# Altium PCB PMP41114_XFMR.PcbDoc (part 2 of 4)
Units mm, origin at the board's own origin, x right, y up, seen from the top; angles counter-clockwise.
Board outline 70 x 173.04 mm, 10 copper layers (Top Layer, Layer 2, Layer 3, Layer 4, Layer 5, Layer 6, Layer 7, Layer 8, Layer 9, Bottom Layer 1), stack 2.98 mm thick; 147 components, 149 nets, 547 pads, 972 vias.
Unrouted connection lines stored in the file: 2.
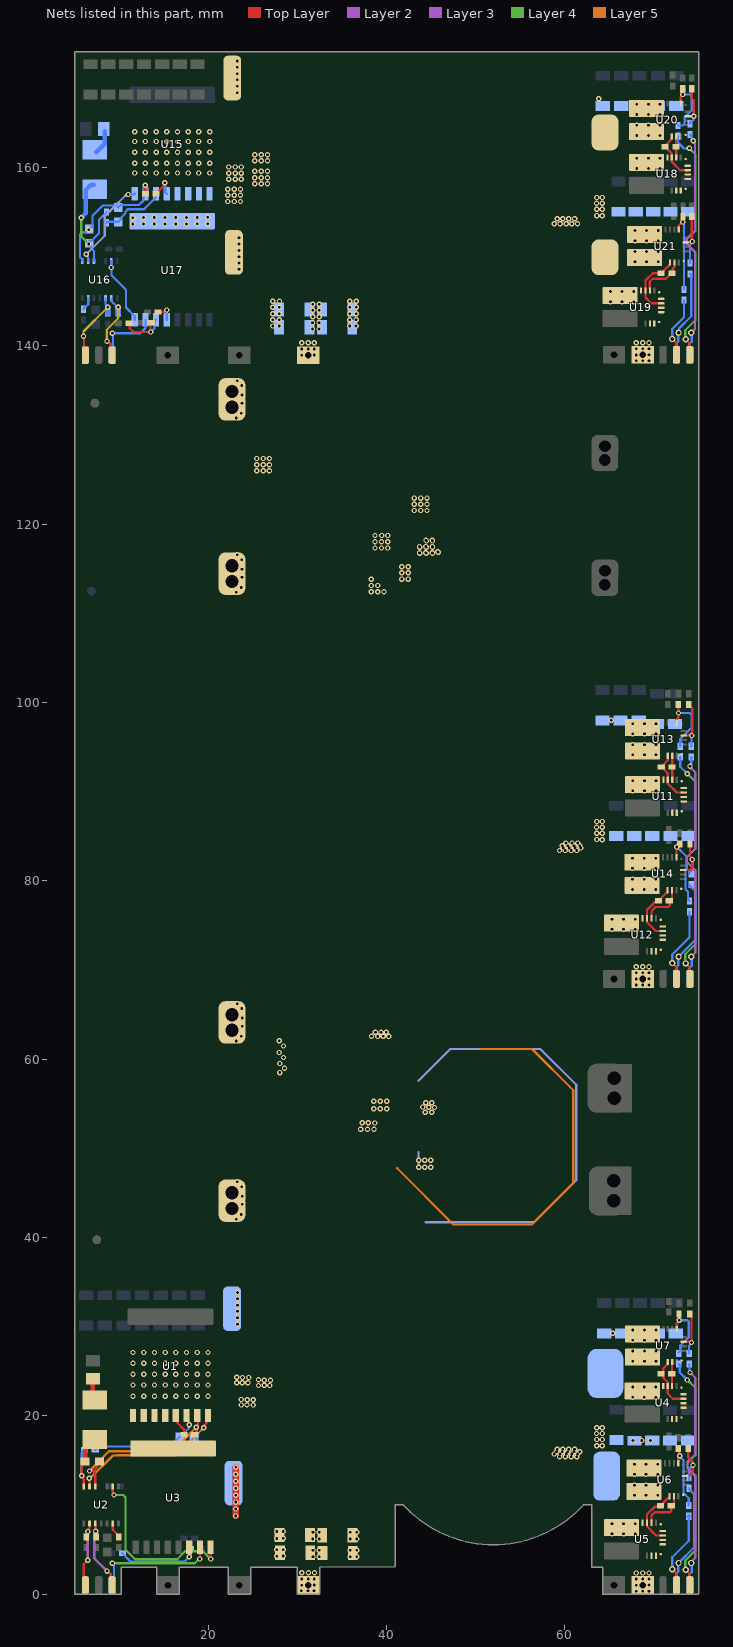
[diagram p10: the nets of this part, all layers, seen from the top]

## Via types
v1: diameter 0.6, hole 0.3, Top Layer to Bottom Layer 1, tented both sides, 748 vias
v2: diameter 0.6, hole 0.3, Layer 2 to Layer 3, tented both sides, 41 vias
v3: diameter 0.6, hole 0.3, Layer 6 to Layer 7, tented both sides, 38 vias
v4: diameter 0.6, hole 0.3, Layer 8 to Layer 9, tented both sides, 35 vias
v5: diameter 0.6, hole 0.3, Layer 4 to Layer 5, tented both sides, 31 vias
v6: diameter 0.6, hole 0.3, Layer 2 to Layer 9, tented both sides, 24 vias
v7: diameter 0.6, hole 0.3, Layer 2 to Layer 5, tented both sides, 22 vias
v8: diameter 0.7, hole 0.4, Top Layer to Bottom Layer 1, tented both sides, 18 vias
v9: diameter 0.6, hole 0.3, Layer 6 to Layer 9, tented both sides, 15 vias

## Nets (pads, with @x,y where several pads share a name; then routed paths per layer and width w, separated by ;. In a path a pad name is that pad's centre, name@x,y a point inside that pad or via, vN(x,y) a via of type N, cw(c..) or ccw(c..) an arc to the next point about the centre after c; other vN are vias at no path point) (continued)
GND-AH_2: C28.2 U4.4 U4.14 U7.8 | length 6.2
  Top Layer w0.254: C28.2@70.789,24.718 70.889,24.718 71.038,24.867 71.038,25.292 71.549,25.804 U7.8@71.549,26.025 ; C28.2@70.865,24.718 71.038,24.545 71.038,24.236 71.526,23.748 71.526,23.335 U4.4@71.528,23.333 71.528,22.488 72.108,21.908 U4.14@73.303,21.908
GND-AH_4: C61.2 U11.4 U11.14 U13.8 | length 5.9
  Top Layer w0.254: C61.2@70.807,92.775 C61.2@70.907,92.775 ; U13.8@71.549,94.025 71.547,94.023 71.547,93.516 71.08,93.048 71.08,92.948 C61.2@70.907,92.775 ; U11.14@73.324,89.908 72.566,89.908 71.549,90.925 U11.4@71.549,91.333 71.549,92.064 71.08,92.534 71.08,92.602 C61.2@70.907,92.775
GND-AH_5: C92.2 U18.4 U18.14 U20.8 | length 5.8
  Top Layer w0.254: C92.2@71.066,162.295 71.018,162.343 C92.2@71.066,162.392 ; C92.2@71.147,162.246 71.247,162.246 C92.2@71.297,162.296 ; C92.2@71.249,162.343 71.349,162.343 71.522,162.17 71.522,162.07 71.998,161.594 71.998,161.14 U18.4@72,161.138 72.002,161.136 72.002,160.622 72.911,159.713 U18.14@73.775,159.713 ; C92.2@71.42,162.419 71.42,162.642 71.99,163.212 U20.8@71.99,163.433
GND-BH_2: C25.2 U5.4 U5.14 U6.8 | length 6.9
  Top Layer w0.254: U5.4@69.21,8.005 69.212,8.003 69.212,7.595 70.227,6.58 U5.14@70.985,6.58 ; U5.4@69.212,8.005 69.212,8.103 69.21,8.105 69.21,8.947 70.099,9.835 70.653,9.835 C25.2@70.731,9.913 ; C25.2@70.802,9.843 71.004,10.045 71.004,10.228 71.331,10.555 71.34,10.555 71.537,10.752 U6.8@71.723,10.752 ; C25.2@70.998,9.75 70.994,9.75 C25.2@71.004,9.74
GND-BH_4: C62.2 U12.4 U12.14 U14.8 | length 6.7
  Top Layer w0.254: U12.4@69.21,75.805 69.212,75.803 69.212,75.355 70.187,74.38 U12.14@70.985,74.38 ; U12.4@69.21,76.005 69.212,76.007 69.212,76.742 70.107,77.638 70.328,77.638 70.501,77.811 70.601,77.811 70.774,77.984 70.774,78.046 71.165,78.438 71.441,78.714 71.514,78.714 71.516,78.716 U14.8@71.516,78.937
GND-BH_5: C93.2 U19.4 U19.14 U21.8 | length 7.3
  Top Layer w0.254: U19.14@70.609,144.779 69.677,144.779 69.034,145.422 69.034,147.338 69.853,148.158 70.9,148.158 71.073,148.331 71.073,148.418 U21.8@71.782,149.127
GND-SW_2: C1.2 C32.2 R2.1 U1.7 U2.11 | length 21.4
  Top Layer w0.254: v1(6.678,13.81) 7.138,13.81 7.491,14.163 7.491,14.574 C1.2@7.787,14.87 ; 7.086,13.762 7.339,13.509 U2.11@7.339,12.08 ; R2.1@18.491,17.882 18.654,18.045 v1(18.654,18.702) 18.654,18.796 18.84,18.982 18.84,19.81 18.763,19.733 U1.7@18.763,20.033
  Layer 5 w0.254: v1(6.678,13.81) 8.874,16.006 9.54,16.006 9.545,16.011 15.962,16.011 17.623,17.672 v1(18.654,18.702)
  Bottom Layer 1 w0.254: v1(18.654,18.702) 18.654,17.35 C32.2@18.672,17.332
GND-SW_5: C63.2 C98.2 R18.1 U15.7 U16.8 | length 15.1
  Top Layer w0.254: v1(12.923,158.022) 12.923,157.092 R18.1@12.942,157.073
  Bottom Layer 1 w0.254: U16.8@5.882,149.522 5.859,149.545 5.859,149.72 5.624,149.956 5.624,152.491 5.881,152.748 6.298,152.748 v1(6.589,153.038) C63.2@6.664,153.114 7.012,153.462 7.012,154.601 8.157,155.745 9.677,155.745 C98.2@9.91,155.513 ; C98.2@9.91,155.525 10.181,155.796 12.216,155.796 12.727,156.308 U15.7@12.727,156.848
  Bottom Layer 1 w0.5: v1(12.923,158.022) 12.937,158.008 U15.7@12.937,157.057
NC1_2: U5.1
NC1_4: U12.1
NC1_5: U19.1
NC2_2: U5.5
NC2_4: U12.5
NC2_5: U19.5
NC3_2: U5.11
NC3_4: U12.11
NC3_5: U19.11
NC4_2: U5.12
NC4_4: U12.12
NC4_5: U19.12
NC5_2: U5.13
NC5_4: U12.13
NC5_5: U19.13
NC6_2: U5.15
NC6_4: U12.15
NC6_5: U19.15
NC7_2: U4.1
NC7_4: U11.1
NC7_5: U18.1
NC8_2: U4.5
NC8_4: U11.5
NC8_5: U18.5
NC9_2: U4.11
NC9_4: U11.11
NC9_5: U18.11
NC10_2: U4.12
NC10_4: U11.12
NC10_5: U18.12
NC11_2: U4.13
NC11_4: U11.13
NC11_5: U18.13
NC12_2: U4.15
NC12_4: U11.15
NC12_5: U18.15
NC13_2: U7.11
NC13_4: U13.11
NC13_5: U20.11
NC14_2: U6.11
NC14_4: U14.11
NC14_5: U21.11
NetC1_1: C1.1 D1.1 R10.1 U2.13 | length 9.1
  Top Layer w0.254: U2.13@6.039,12.08 6.039,12.955 5.802,13.193 v1(5.802,13.286) 5.814,13.299 5.814,14.522 5.898,14.606 C1.1@6.205,14.606
  Top Layer w0.5: C1.1@6.187,14.87 6.187,16.509 7.017,17.339 D1.1@7.284,17.339
  Bottom Layer 1 w0.254: v1(5.802,13.286) 5.802,15.845 5.856,15.899 5.856,15.999 6.029,16.172 R10.1@6.129,16.172
NetC23_1: C23.1 R6.1 U6.14 | length 5.8
  Top Layer w0.254: U6.14@73.5,13.25 73.502,13.252 73.91,13.252 74.371,13.713 v1@74.371,14.487 ; C23.1@73.85,16.334 73.85,15.342 74.329,14.863 74.329,14.492 v1(74.371,14.45)
  Bottom Layer 1 w0.254: R6.1@73.924,12.773 73.924,14.004 v1(74.371,14.45)
NetC24_1: C24.1 R5.1 U6.2 | length 7.6
  Top Layer w0.254: C24.1@72.725,16.334 72.837,16.222 72.804,16.189 72.804,15.599 v1(72.87,15.532) 72.87,15.439 72.727,15.296 U6.2@72.727,14.898
  Bottom Layer 1 w0.254: v1(72.87,15.532) 72.87,15.439 73.297,15.011 73.297,11.337 73.893,10.742 R5.1@73.893,9.933
NetC26_1: C26.1 R8.1 U7.14 | length 5.3
  Top Layer w0.254: U7.14@73.324,28.3 74.041,28.3 74.19,28.449 C26.1@74.19,31.431
  Bottom Layer 1 w0.254: R8.1@73.931,26.99 73.931,27.849 74.21,28.128 v1(74.21,28.221)
NetC27_1: C27.1 R7.1 U7.2 | length 6.9
  Top Layer w0.254: U7.2@72.549,29.725 72.549,30.338 72.804,30.592 C27.1@72.804,31.431
  Bottom Layer 1 w0.254: R7.1@72.769,27.104 72.942,27.277 72.942,27.84 73.889,28.787 73.889,30.557 73.74,30.705 v1(72.819,30.705)
NetC32_1: C32.1 R10.2 U1.6 | length 13
  Top Layer w0.254: U1.6@17.563,19.958 17.786,19.735 17.786,19.163 17.865,19.084 v1(17.865,18.991)
  Bottom Layer 1 w0.254: R10.2@7.329,16.172 7.502,16.345 7.633,16.345 7.854,16.565 15.72,16.565 16.798,17.644 C32.1@16.823,17.644 16.848,17.644 17.799,18.594 17.799,18.925 v1(17.865,18.991)
NetC38_2: C38.2 R12.2 U3.6 | length 10.9
  Top Layer w0.254: U3.6@17.863,5.251 17.868,5.247 17.868,4.191 v1(17.873,4.186)
  Bottom Layer 1 w0.254: R12.2@10.363,4.568 11.274,3.657 17.353,3.657 17.873,4.176 v1(17.873,4.186) ; v1@17.878,4.181 17.878,4.285 18.026,4.433 C38.2@18.026,5.101 ; v1@17.934,4.247 17.934,4.891 C38.2@17.994,4.951
NetC39_1: C39.1 R25.2 U17.6 | length 5.8
  Top Layer w0.254: R25.2@11.11,142.526 11.188,142.447 11.188,141.993 11.629,141.553 v1(13.534,141.553) 13.534,142.483 C39.1@13.644,142.592
  Bottom Layer 1 w0.254: v1(13.534,141.553) 13.976,141.995 13.976,142.748 U17.6@14.15,142.922
NetC57_1: C57.1 R15.1 U13.14 | length 5.5
  Top Layer w0.254: U13.14@73.324,96.3 73.89,96.3 74.282,96.691 74.282,99.3 74.04,99.542 C57.1@73.874,99.542
  Bottom Layer 1 w0.254: R15.1@74.174,95.1 74.205,95.131 74.205,96.269 v1(74.236,96.3)
NetC58_1: C58.1 R13.1 U13.2 | length 7.7
  Top Layer w0.254: U13.2@72.549,97.725 72.549,98.133 72.75,98.334 v1(72.75,98.819) ; v1@72.734,98.835 C58.1@72.734,99.791
  Bottom Layer 1 w0.254: v1(72.75,98.819) 73.978,98.819 74.236,98.561 74.236,97.193 72.944,95.901 R13.1@72.944,95.1
NetC59_1: C59.1 R16.1 U14.14 | length 5.4
  Top Layer w0.254: U14.14@73.514,81.21 74.078,81.21 74.299,81.43 v1(74.299,82.394) 74.299,82.488 74.032,82.754 C59.1@74.032,84.132
  Bottom Layer 1 w0.254: R16.1@73.978,80.773 73.978,80.873 74.299,81.194 v1(74.299,82.394)
NetC60_1: C60.1 R14.1 U14.2 | length 8.3
  Top Layer w0.254: U14.2@72.516,82.637 v1@72.516,83.737
  Top Layer w0.6: v1@72.566,83.811 C60.1@72.887,84.132
  Bottom Layer 1 w0.254: v1(72.566,83.788) 73.657,82.697 73.657,81.415 73.524,81.281 73.524,79.064 73.805,78.783 73.805,77.899 R14.1@73.978,77.726
NetC63_1: C63.1 D3.1 R11.1 U16.10 | length 14.8
  Layer 9 w0.254: v1(5.768,154.359) 5.768,152.259 v1(6.589,151.438)
  Bottom Layer 1 w0.254: C63.1@6.48,151.313 6.526,151.268 6.734,151.268 6.937,151.065 6.937,150.857 7.182,150.611 U16.10@7.182,149.522 ; v1(6.589,151.438) C63.1@6.589,151.463 ; C63.1@6.664,151.811 6.664,151.539 C63.1@6.589,151.463 ; R11.1@8.592,155.018 8.592,154.918 8.419,154.745 8.357,154.745 7.758,154.146 7.758,152.632 C63.1@6.589,151.463
  Bottom Layer 1 w0.5: v1(5.768,154.359) 5.768,154.386 6.236,154.854 6.236,157.46 6.873,158.098 D3.1@7.165,158.098
NetC88_1: C88.1 R23.1 U20.14 | length 4.7
  Top Layer w0.254: U20.14@73.775,165.767 73.777,165.769 74.185,165.769 74.452,166.036 74.452,167.557 74.242,167.767 C88.1@74.242,168.842
  Bottom Layer 1 w0.254: R23.1@74.053,164.974 74.053,165.04 74.207,165.194 74.272,165.194 74.421,165.343 74.421,165.736 v1(74.452,165.767)
NetC89_1: C89.1 R21.1 U20.2 | length 7
  Top Layer w0.254: U20.2@73,167.192 73,167.887 v1@73.209,168.096
  Top Layer w0.6: v1(73.209,168.192) C89.1@73.209,168.842
  Bottom Layer 1 w0.254: R21.1@72.681,164.712 72.684,164.714 73.214,164.714 73.407,164.908 73.407,165.609 74.226,166.428 74.226,168.008 74.042,168.192 v1(73.209,168.192)
NetC90_1: C90.1 R24.1 U21.14 | length 5.9
  Top Layer w0.254: U21.14@73.561,151.627 73.969,151.627 74.242,151.9 C90.1@74.242,154.512
  Bottom Layer 1 w0.254: R24.1@74.034,149.286 74.034,151.359 74.3,151.624 v1(74.3,151.718)
NetC91_1: C91.1 R22.1 U21.2 | length 9.3
  Top Layer w0.254: U21.2@72.784,153.05 72.784,153.508 73.102,153.827 73.147,153.827 73.241,153.921 73.241,153.966 73.274,153.998 73.274,154.48 C91.1@73.241,154.512
  Bottom Layer 1 w0.254: v1(73.203,153.901) 73.203,153.807 73.366,153.645 R22.1@73.366,146.334
NetC98_1: C98.1 R11.2 U15.6 | length 7.3
  Bottom Layer 1 w0.254: R11.2@8.592,153.818 8.686,153.913 C98.1@9.91,153.913 10.258,154.261 10.258,154.423 10.712,154.877 10.712,155.047 11.007,155.342 12.822,155.342 14.15,156.671 U15.6@14.15,157.071
NetD1_2: D1.2 R1.2 | length 2.8
  Top Layer w0.254: D1.2@7.063,21.979 D1.2@7.284,21.759 ; R1.2@7.063,24.149 R1.2@7.284,23.929
  Top Layer w0.5: D1.2@7.063,21.979 R1.2@7.063,24.149
NetD3_2: D3.2 R17.2 | length 2.8
  Bottom Layer 1 w0.5: D3.2@7.423,161.71 8.376,162.662 R17.2@8.376,164.084
NetLabel5_2: U5.10
NetLabel5_4: U12.10
NetLabel5_5: U19.10
NetLabel6_2: U5.9
NetLabel6_4: U12.9
NetLabel6_5: U19.9
NetLabel7_2: U4.10
NetLabel7_4: U11.10
NetLabel7_5: U18.10
NetLabel8_2: U4.9
NetLabel8_4: U11.9
NetLabel8_5: U18.9
NetR2_2: R2.2 U1.5 | length 2.4
  Top Layer w0.254: U1.5@16.48,19.926 16.586,19.819 16.586,19.159 17.291,18.454 R2.2@17.291,17.882
NetR3_2: R3.2 U2.6 | length 1.8
  Top Layer w0.254: U2.6@9.289,7.93 9.289,7.209 9.98,6.518 R3.2@9.98,6.418
NetR18_2: R18.2 U15.5 | length 3
  Top Layer w0.254: R18.2@14.142,157.073 14.242,157.073 14.415,157.246 14.415,157.346 15.053,157.985 15.053,158.224 v1(15.119,158.29)
  Bottom Layer 1 w0.254: v1(15.119,158.29) 15.185,158.224 15.185,157.236 U15.5@15.35,157.071
NetR19_2: R19.2 U16.6 | length 1.5
  Bottom Layer 1 w0.254: R19.2@6.01,144.11 6.01,144.21 6.183,144.383 6.249,144.383 6.532,144.666 U16.6@6.532,145.372
NetR20_2: R20.2 U17.5 | length 2.2
  Top Layer w0.254: R20.2@14.366,143.797 15.049,143.797 15.274,144.022 v1(15.358,144.022)
  Bottom Layer 1 w0.254: U17.5@15.35,142.922 15.354,142.926 15.354,144.018 v1(15.358,144.022)
NetU1_8: U1.8 U2.12 | length 17.8
  Top Layer w0.254: v1(6.666,12.981) 6.678,12.97 6.678,12.092 U2.12@6.689,12.08 ; v1(19.486,18.646) 19.552,18.713 19.552,18.922 19.762,19.132 19.762,19.762 U1.8@20.113,20.113
  Layer 5 w0.254: v1(6.666,12.981) 6.736,12.981 9.307,15.552 9.728,15.552 9.733,15.557 16.396,15.557 v1(19.486,18.646)
NetU2_9: U2.9 U3.8 | length 20.3
  Top Layer w0.254: U2.9@9.289,12.08 9.289,11.346 9.432,11.204 v1(9.432,11.11) ; v1(20.263,3.936) U3.8@20.263,5.251
  Layer 4 w0.254: v1(9.432,11.11) 10.459,11.11 10.726,10.844 10.726,4.979 11.787,3.918 16.52,3.918 17.42,4.817 19.382,4.817 v1(20.263,3.936)
NetU15_8: U15.8 U16.9 | length 10.5
  Layer 6 w0.254: v1(6.31,150.271) 8.392,152.353 8.392,154.529 9.376,155.513 10.702,156.839 10.789,156.839 10.926,156.976 v1(11.02,156.976)
  Layer 8 w0.254: v1@10.975,156.931 v1(11.02,156.976)
  Layer 9 w0.254: v1@10.994,156.95 v1(11.02,156.976)
  Bottom Layer 1 w0.254: v1(6.31,150.271) 6.31,150.178 6.509,149.978 6.509,149.545 U16.9@6.532,149.522 ; v1(11.02,156.976) 11.655,156.976 U15.8@11.75,157.071
NetU16_12: U16.12 U17.8 | length 7.7
  Bottom Layer 1 w0.254: U16.12@9.132,149.522 9.134,149.52 9.134,148.789 v1(9.136,148.788) 9.136,147.939 10.775,146.3 10.775,144.297 11.75,143.322 U17.8@11.75,142.922
PGND_2: C12.2 C13.2 C14.2 C15.2 C16.2 C17.2 C18.2 C19.2 C20.2 C33.2 pad.S7@68.74,1 U6.6 U7.6
  other v1: 68.008,0.321 68.748,0.321 69.431,0.321 68.008,0.984 69.431,1.016 68.008,1.691 68.731,1.691 69.431,1.691 68.008,2.366 68.731,2.366 69.431,2.366 67.8,13.435 69.1,13.435 70.4,13.435 67.8,14.575 69.1,14.575 70.4,14.575 67.634,17.233 68.622,17.233 69.61,17.233 67.624,28.485 68.924,28.485 70.224,28.485 65.367,29.242 67.624,29.625 68.924,29.625 70.224,29.625
PGND_4: C34.2 C46.2 C47.2 C48.2 C49.2 C50.2 C51.2 C52.2 C53.2 C54.2 pad.S7@68.74,69 U13.6 U14.6
  other v1: 68.008,68.321 68.748,68.321 69.431,68.321 68.008,68.984 69.431,69.016 68.008,69.691 68.731,69.691 69.431,69.691 68.008,70.366 68.731,70.366 69.431,70.366 67.591,81.397 68.891,81.397 70.191,81.397 67.591,82.537 68.891,82.537 70.191,82.537 67.624,96.485 68.924,96.485 70.224,96.485 67.624,97.625 68.924,97.625 70.224,97.625 65.186,98.022
PGND_5: C35.2 C77.2 C78.2 C79.2 C80.2 C81.2 C82.2 C83.2 C84.2 C85.2 pad.S7@68.74,139 U20.6 U21.6
  other v1: 68.008,138.321 68.748,138.321 69.431,138.321 68.008,138.984 69.431,139.016 68.008,139.691 68.731,139.691 69.431,139.691 68.008,140.366 68.731,140.366 69.431,140.366 67.859,151.81 69.159,151.81 70.459,151.81 67.859,152.95 69.159,152.95 70.459,152.95 68.075,165.952 69.375,165.952 70.675,165.952 68.075,167.092 69.375,167.092 70.675,167.092 63.817,167.724
Pri-Mid1_2: C3.1 C4.1 C5.1 C6.1 pad.8@22.842,12.447 | length 5.5
  Top Layer w0.7: v1(23.092,8.755) v1(23.092,14.227)
  other v1: 35.939,4.186 36.646,4.189 27.698,4.259 28.406,4.263 35.939,4.913 36.646,4.913 27.698,4.986 28.406,4.986 35.932,6.169 36.64,6.173 27.692,6.243 28.399,6.246 35.939,6.952 36.646,6.952 27.698,7.026 28.406,7.026 23.092,9.537 23.095,10.319 23.092,11.1 23.092,11.882 23.092,12.664 23.092,13.446
Pri-Mid1_5: C65.1 C66.1 C67.1 C68.1 pad.8@22.875,150.486
  other v1: 27.228,142.231 27.952,142.231 35.857,142.231 36.58,142.231 27.228,142.927 27.952,142.927 35.857,142.927 36.58,142.927 27.246,143.622 27.969,143.622 35.874,143.622 36.598,143.622 27.246,144.318 27.969,144.318 35.874,144.318 36.598,144.318 27.246,145.014 27.986,145.014 35.874,145.014 36.615,145.014 23.444,148.581 23.444,149.304 23.44,150.012 23.44,150.707 23.44,151.431 23.448,152.138
Pri-Middle_2: C3.2 C4.2 C5.2 C6.2 pad.P9@31.21,1
  other v1: 30.439,0.379 31.18,0.379 31.863,0.379 30.478,0.984 31.901,1.016 30.478,1.691 31.201,1.691 31.901,1.691 30.497,2.387 31.237,2.387 31.92,2.387 31.742,4.186 32.45,4.189 31.742,4.913 32.45,4.913 31.736,6.169 32.444,6.173 31.742,6.952 32.45,6.952
Pri-Middle_5: C65.2 C66.2 C67.2 C68.2 pad.P9@31.21,138.962
  other v1: 30.478,138.945 31.901,138.978 30.478,139.653 31.201,139.653 31.901,139.653 30.478,140.348 31.219,140.348 31.901,140.348 31.692,141.897 32.416,141.897 31.692,142.592 32.416,142.592 31.709,143.288 32.433,143.288 31.709,143.983 32.433,143.983 31.709,144.679 32.45,144.679
Pri-SW_2: pad.8@22.665,32.008 pad.8@22.666,43.25 pad.8@22.666,45.01 pad.8@22.666,63.24 pad.8@22.666,65 U1.1 U1.2 U1.3 U1.4 U3.9 | length 101.3
  Layer 5 w0.254: 41.186,47.749 47.477,41.458 56.289,41.458 60.934,46.103 60.934,56.511 56.315,61.13 50.419,61.13
  Layer 6 w0.254: v3@43.592,47.887 v3(43.592,48.651) 43.592,49.577 ; 43.592,57.579 47.142,61.13 57.249,61.13 61.263,57.115 61.263,46.413 56.563,41.712 44.355,41.712
  Layer 9 w0.254: pad.8@22.665,45.01 pad.8@22.665,46.098
  Bottom Layer 1 w0.254: pad.8@22.665,45.01 pad.8@22.665,46.098
  other v1: 11.563,22.2 12.763,22.2 13.963,22.2 15.163,22.2 16.363,22.2 17.563,22.2 18.763,22.2 19.963,22.2 11.563,23.452 12.763,23.452 13.963,23.452 15.163,23.452 16.363,23.452 17.563,23.452 18.763,23.452 19.963,23.452 11.563,24.672 12.763,24.672 13.963,24.672 15.163,24.672 16.363,24.672 17.563,24.672 18.763,24.672 19.963,24.672 11.563,25.892 12.763,25.892 13.963,25.892 15.163,25.892 16.363,25.892 17.563,25.892 18.763,25.892 19.963,25.892 11.563,27.1 12.763,27.1 13.963,27.1 15.163,27.1 16.363,27.1 17.563,27.1 18.763,27.1 19.963,27.1 23.276,30.278 23.276,31.001 23.273,31.709 23.273,32.404 23.273,33.127 23.28,33.835 23.145,42.044 23.692,42.573 23.796,43.711 23.796,44.629 23.752,45.682 23.247,46.231 23.145,62.034 23.692,62.563 23.796,63.701 23.796,64.619 23.752,65.672 23.247,66.221
  other v2: 28.016,58.493 28.56,58.964 28.016,59.504 28.432,60.182 27.968,60.741 28.432,61.482 27.968,62.063
  other v3: 23.186,23.696 24.449,23.696 23.822,23.719 24.525,24.288 23.186,24.318 23.839,24.297 43.592,47.889 44.271,47.889 44.947,47.889 44.271,48.651 44.947,48.651
  other v5: 23.713,21.206 25.051,21.206 24.349,21.229 25.051,21.799 23.713,21.828 24.366,21.808 44.354,54.056 45.076,54.056 45.38,54.571 44.739,54.599 44.057,54.629 44.389,55.103 45.076,55.103
  other v6: 25.635,23.399 26.899,23.399 26.272,23.423 26.289,24.001 26.974,23.992 25.635,24.022 37.853,52.125 38.593,52.133 37.085,52.135 37.268,52.869 37.936,52.869 38.664,52.846
  other v7: 38.303,62.556 39,62.549 39.623,62.556 40.25,62.549 38.75,63.017 39.371,63.017 39.966,63.017
  other v9: 38.578,54.424 39.295,54.424 40.012,54.424 38.578,55.271 39.295,55.271 40.012,55.271
Pri-SW_5: pad.8@22.659,113.579 pad.8@22.659,115.34 pad.8@22.659,133.121 pad.8@22.659,134.881 pad.8@22.698,170.047 U15.1 U15.2 U15.3 U15.4 U17.9
  other v1: 23.137,112.374 23.684,112.902 23.789,114.041 23.789,114.958 23.745,116.012 23.24,116.561 23.137,131.916 23.684,132.444 23.789,133.583 23.789,134.5 23.745,135.554 23.24,136.102 11.539,153.667 12.742,153.671 13.944,153.674 15.147,153.677 16.35,153.68 17.552,153.684 18.755,153.687 19.958,153.69 11.539,154.391 12.742,154.394 13.944,154.397 15.147,154.4 16.35,154.404 17.552,154.407 18.755,154.41 19.958,154.413 11.75,159.402 12.95,159.402 14.15,159.402 15.35,159.402 16.55,159.402 17.75,159.402 18.95,159.402 20.15,159.402 11.75,160.49 12.95,160.49 14.15,160.49 15.35,160.49 16.55,160.49 17.75,160.49 18.95,160.49 20.15,160.49 11.75,161.71 12.95,161.71 14.15,161.71 15.35,161.71 16.55,161.71 17.75,161.71 18.95,161.71 20.15,161.71 11.75,162.93 12.95,162.93 14.15,162.93 15.35,162.93 16.55,162.93 17.75,162.93 18.95,162.93 20.15,162.93 11.75,164.01 12.95,164.01 14.15,164.01 15.35,164.01 16.55,164.01 17.75,164.01 18.95,164.01 20.15,164.01 23.238,168.406 23.238,169.13 23.235,169.837 23.235,170.532 23.235,171.256 23.242,171.963
  other v2: 43.733,116.73 44.456,116.73 45.156,116.73 45.787,116.841 43.733,117.426 44.456,117.426 45.156,117.426 44.474,118.121 45.156,118.121
  other v3: 38.705,117.341 39.428,117.341 40.128,117.341 38.705,118.036 39.428,118.036 40.128,118.036 38.705,118.732 39.445,118.732 40.128,118.732 22.289,158.681 23.012,158.681 23.712,158.681 22.289,159.376 23.012,159.376 23.712,159.376 22.289,160.072 23.03,160.072 23.712,160.072
  other v4: 25.437,125.987 26.161,125.987 26.86,125.987 25.437,126.683 26.161,126.683 26.86,126.683 25.437,127.378 26.178,127.378 26.86,127.378
  other v5: 43.688,116.806 44.411,116.806 45.111,116.806 45.742,116.917 43.688,117.501 44.411,117.501 45.111,117.501 44.429,118.197 45.111,118.197 22.193,156.191 22.916,156.191 23.616,156.191 22.193,156.887 22.916,156.887 23.616,156.887 22.193,157.582 22.933,157.582 23.616,157.582
  other v6: 38.295,112.431 39.019,112.431 39.718,112.431 38.295,113.126 39.019,113.126 38.295,113.822 25.216,160.764 25.939,160.764 26.639,160.764 25.216,161.459 25.956,161.459 26.639,161.459
  other v7: 41.7,113.846 42.423,113.846 41.7,114.542 42.423,114.542 41.7,115.237 42.423,115.237 25.216,158.182 25.939,158.182 26.639,158.182 25.216,158.878 25.939,158.878 26.639,158.878 25.216,159.574 25.956,159.574 26.639,159.574
  other v9: 43.105,121.54 43.829,121.54 44.528,121.54 43.105,122.236 43.829,122.236 44.528,122.236 43.105,122.931 43.846,122.931 44.528,122.931
PWMH_2: C10.1 pad.P1@6.216,1 U2.2 | length 7.9
  Top Layer w0.254: pad.P1@6.216,1 6.048,1.168 6.048,3.339 v1(6.496,3.788) v1(6.496,3.788) ; v1@6.496,7.105 6.689,7.299 U2.2@6.689,7.93
  Top Layer w0.5: C10.1@6.323,6.405 6.429,6.512 6.429,6.945 v1(6.496,7.011) v1@6.496,7.105
  Layer 3 w0.254: v1(6.496,3.788) v1(6.496,7.011)
PWMH_5: C76.1 pad.P1@6.216,138.962 U16.3 | length 8.3
  Top Layer w0.254: v1(6.01,141.101) 6.076,141.035 6.076,139.101 pad.P1@6.216,138.962
  Layer 7 w0.254: v1(6.01,141.101) 6.01,141.603 v1(8.733,144.326)
  Layer 8 w0.254: v1(6.01,141.101) v1@6.03,141.122
  Bottom Layer 1 w0.254: U16.3@8.482,145.372 8.482,144.666 v1@8.733,144.416
  Bottom Layer 1 w0.6: C76.1@8.733,143.676 v1@8.733,144.295
PWML_2: C11.1 pad.P5@9.216,1 U2.3 | length 8.5
  Top Layer w0.254: U2.3@7.339,7.93 7.362,7.907 v1(7.362,7.042) ; v1(8.639,2.578) 8.733,2.578 9.065,2.246 9.065,1.151 pad.P5@9.216,1
  Top Layer w0.5: v1(7.362,7.042) 7.392,7.013 C11.1@7.392,6.405
  Layer 3 w0.254: v1@7.362,6.948 7.216,6.802 7.216,4.002 v1(8.639,2.578)
  Layer 2 w0.254: v1@7.362,6.948 v1(7.362,7.042)
PWML_5: C75.1 pad.P5@9.216,138.962 U16.2 | length 8.1
  Top Layer w0.254: v1(8.639,140.54) 8.733,140.54 9.065,140.208 9.065,139.112 pad.P5@9.216,138.962
  Layer 7 w0.254: v1(8.639,140.54) 8.602,140.578 8.602,141.804 9.91,143.112 v1(9.91,144.326)
  Bottom Layer 1 w0.254: U16.2@9.14,145.227 9.155,145.212 9.155,145.019 9.848,144.326 v1(9.91,144.326)
  Bottom Layer 1 w0.6: C75.1@9.91,143.676 v1(9.91,144.326)
Sec-SWA_2: pad.8@64.553,24.744 pad.8@64.691,13.221 U4.6 U5.6 U6.7 U7.7
  other v1: 65.285,6.765 66.585,6.765 67.885,6.765 65.285,7.905 66.585,7.905 67.885,7.905 67.8,11.075 69.1,11.075 70.4,11.075 67.8,12.215 69.1,12.215 70.4,12.215 64.209,16.622 63.581,16.637 63.568,17.334 64.209,17.334 63.554,18.018 64.195,18.018 63.568,18.659 64.209,18.659 67.603,22.093 68.903,22.093 70.203,22.093 67.603,23.233 68.903,23.233 70.203,23.233 67.624,26.125 68.924,26.125 70.224,26.125 67.624,27.265 68.924,27.265 70.224,27.265
  other v2: 58.821,15.705 59.462,15.705 60.14,15.705 60.781,15.705 61.422,15.705 59.129,16.255 59.77,16.255 60.448,16.255 61.089,16.255
  other v4: 59.39,15.397 60.031,15.397 60.708,15.397 61.349,15.397 59.056,15.947 59.697,15.947 60.339,15.947 61.016,15.947 61.657,15.947
Sec-SWA_5: pad.8@64.5,163.935 pad.8@64.507,149.937 U18.6 U19.6 U20.7 U21.7
  other v1: 65.109,144.964 66.409,144.964 67.709,144.964 65.109,146.104 66.409,146.104 67.709,146.104 67.859,149.45 69.159,149.45 70.459,149.45 67.859,150.59 69.159,150.59 70.459,150.59 63.581,154.619 64.209,154.604 63.568,155.316 64.209,155.316 63.554,156 64.195,156 63.568,156.641 64.209,156.641 68.075,159.898 69.375,159.898 70.675,159.898 68.075,161.038 69.375,161.038 70.675,161.038 68.075,163.592 69.375,163.592 70.675,163.592 68.075,164.732 69.375,164.732 70.675,164.732
  other v2: 58.821,153.705 59.462,153.705 60.14,153.705 60.781,153.705 61.422,153.705 59.129,154.255 59.77,154.255 60.448,154.255 61.089,154.255
  other v4: 58.821,153.705 59.462,153.705 60.14,153.705 60.781,153.705 61.422,153.705 59.129,154.255 59.77,154.255 60.448,154.255 61.089,154.255
Sec-SWB_4: U11.6 U12.6 U13.7 U14.7
  other v1: 65.285,74.565 66.585,74.565 67.885,74.565 65.285,75.705 66.585,75.705 67.885,75.705 67.591,79.037 68.891,79.037 70.191,79.037 67.591,80.177 68.891,80.177 70.191,80.177 63.581,84.637 64.209,84.622 63.568,85.334 64.209,85.334 63.554,86.018 64.195,86.018 63.568,86.659 64.209,86.659 67.624,90.093 68.924,90.093 70.224,90.093 67.624,91.233 68.924,91.233 70.224,91.233 67.624,94.125 68.924,94.125 70.224,94.125 67.624,95.265 68.924,95.265 70.224,95.265
  other v2: 59.808,83.685 60.486,83.685 61.127,83.685 61.768,83.685 60.116,84.234 60.794,84.234 61.435,84.234
  other v3: 59.39,83.397 60.031,83.397 60.708,83.397 61.349,83.397 59.697,83.947 60.339,83.947 61.016,83.947 61.657,83.947
  other v4: 59.39,83.397 60.031,83.397 60.708,83.397 61.349,83.397 59.697,83.947 60.339,83.947 61.016,83.947 61.657,83.947
SRAH_2: pad.S2@74.015,1 R8.2 | length 26.1
  Layer 3 w0.254: v1(74.032,24.848) 74.619,24.262 74.619,15.683 73.744,14.808 73.744,14.111 74.619,13.236 74.619,4.053 74.174,3.609 v8(74.174,3.488)
  Bottom Layer 1 w0.254: R8.2@73.931,25.79 73.982,25.74 73.982,24.899 v1(74.032,24.848) ; pad.S2@74.015,1 74.015,2.235 74.24,2.46 74.24,3.021 74.237,3.024 74.237,3.426 v8(74.174,3.488)
SRAH_4: pad.S2@74.015,69 R15.2 | length 26.3
  Layer 3 w0.254: v1(74.032,92.848) 74.032,92.755 74.619,92.168 74.619,83.602 73.672,82.654 73.672,82.135 74.619,81.187 74.619,71.932 v8(74.174,71.488)
  Bottom Layer 1 w0.254: pad.S2@74.015,69 74.015,70.235 74.24,70.46 74.24,71.021 74.237,71.024 74.237,71.426 v8(74.174,71.488) ; v1(74.032,92.848) 74.032,92.942 74.174,93.084 R15.2@74.174,93.9
SRAH_5: pad.S2@74.015,139 R23.2 | length 26.1
  Layer 3 w0.254: v8(74.174,141.488) 74.596,141.91 74.596,150.535 73.673,151.458 73.673,151.978 74.596,152.901 74.596,162.703 74.391,162.908 v1(74.391,163.001)
  Layer 5 w0.254: v8(74.174,141.488) v8@74.174,141.563
  Bottom Layer 1 w0.254: pad.S2@74.015,139 74.015,140.235 74.24,140.46 74.24,141.021 74.237,141.024 74.237,141.426 v8(74.174,141.488) ; R23.2@74.034,163.721 74.207,163.548 74.207,163.185 v1(74.391,163.001)
SRAL_2: pad.S1@74.015,1 R7.2 | length 27
  Top Layer w0.254: v8(73.563,2.741) 74.015,2.289 pad.S1@74.015,1
  Layer 4 w0.254: v8(73.563,2.741) 73.501,2.803 73.501,3.204 73.497,3.208 73.497,3.768 74.619,4.89 74.619,13.315 73.744,14.19 73.744,14.71 74.619,15.585 74.619,23.132 v1(73.744,24.007)
  Bottom Layer 1 w0.254: R7.2@72.769,25.79 72.889,25.67 72.889,24.862 v1(73.744,24.007)
SRAL_4: pad.S1@74.015,69 R13.2 | length 27.1
  Top Layer w0.254: v8(73.563,70.741) 74.015,70.289 pad.S1@74.015,69
  Layer 4 w0.254: v8(73.563,70.741) 73.501,70.803 73.501,71.204 73.497,71.208 73.497,71.768 74.619,72.89 74.619,81.187 73.672,82.135 73.672,82.654 74.619,83.602 74.619,91.132 v1(73.744,92.007)
  Bottom Layer 1 w0.254: R13.2@72.944,93.9 72.944,92.807 v1(73.744,92.007)
SRAL_5: pad.S1@74.015,139 R21.2 | length 27.2
  Top Layer w0.254: v8(73.563,140.741) 74.015,140.289 pad.S1@74.015,139
  Layer 4 w0.254: v8(73.563,140.741) 73.501,140.803 73.501,141.204 73.497,141.208 73.497,141.768 74.619,142.89 74.619,150.512 73.673,151.458 73.673,151.978 74.619,152.924 74.619,161.504 v1(73.969,162.154)
  Layer 5 w0.254: v8@73.501,140.803 v8(73.563,140.741)
  Bottom Layer 1 w0.254: R21.2@72.681,163.512 72.681,162.838 73.366,162.154 v1(73.969,162.154)
SRBH_2: pad.S4@72.515,1 R6.2 | length 12
  Layer 3 w0.254: v8(72.75,3.488) v8@72.795,3.533
  Bottom Layer 1 w0.254: pad.S4@72.515,1 72.515,2.283 72.726,2.495 72.726,3.464 v8(72.75,3.488) 74.52,5.258 74.52,11.177 73.924,11.773 R6.2@73.924,11.873
SRBH_4: pad.S4@72.515,69 R16.2 | length 11.8
  Layer 3 w0.254: v8(72.75,71.488) v8@72.795,71.533
  Bottom Layer 1 w0.254: pad.S4@72.515,69 72.515,70.283 72.726,70.495 72.726,71.464 v8(72.75,71.488) 74.619,73.357 74.619,78.832 73.978,79.473 R16.2@73.978,79.573
SRBH_5: pad.S4@72.515,139 R24.2 | length 9.9
  Layer 3 w0.254: v8(72.75,141.488) v8@72.795,141.533
  Bottom Layer 1 w0.254: pad.S4@72.515,139 72.515,140.283 72.726,140.495 72.726,141.464 72.805,141.543 72.805,141.959 74.174,143.329 74.174,147.946 R24.2@74.034,148.086
SRBL_2: pad.S3@72.515,1 R5.2 | length 8.7
  Top Layer w0.254: v8(72.049,2.775) 72.515,2.31 pad.S3@72.515,1
  Layer 3 w0.254: v8(72.049,2.775) v8@72.073,2.799
  Bottom Layer 1 w0.254: v8(72.049,2.775) 72.049,4.126 73.893,5.969 R5.2@73.893,8.733
  Bottom Layer 1 w0.5: R5.2@73.889,8.73 R5.2@73.893,8.733
SRBL_4: pad.S3@72.515,69 R14.2 | length 8.6
  Top Layer w0.254: v8(72.049,70.775) 72.515,70.31 pad.S3@72.515,69
  Layer 3 w0.254: v8(72.049,70.775) v8@72.073,70.799
  Bottom Layer 1 w0.254: v8(72.049,70.775) 72.049,71.739 72.073,71.763 72.073,71.768 72.944,72.639 73.978,73.673 R14.2@73.978,76.526
SRBL_5: pad.S3@72.515,139 R22.2 | length 6.9
  Top Layer w0.254: v8@72.034,140.791 v8(72.049,140.775) 72.515,140.31 pad.S3@72.515,139
  Layer 3 w0.254: v8(72.049,140.775) v8@72.073,140.799
  Bottom Layer 1 w0.254: v8(72.049,140.775) 72.049,141.895 73.366,143.211 R22.2@73.366,145.134
VCC-AH_2: C28.1 U4.3 U7.9 | length 2.7
  Top Layer w0.254: U4.3@72.028,23.333 72.028,25.782 72.049,25.804 U7.9@72.049,26.025
VCC-AH_4: C61.1 U11.3 U13.9 | length 2.7
  Top Layer w0.254: U11.3@72.049,91.333 U13.9@72.049,94.025
VCC-AH_5: C92.1 U18.3 U20.9 | length 2.3
  Top Layer w0.254: U20.9@72.49,163.433 72.49,162.246 72.5,162.236 U18.3@72.5,161.138
VCC-BH_2: C25.1 U5.3 U6.9 | length 4.8
  Top Layer w0.254: U5.3@69.71,8.105 69.712,8.107 69.712,8.807 70.084,9.178 71.782,9.178 71.931,9.327 C25.1@71.931,9.913 ; C25.1@72.238,9.913 U6.9@72.238,10.953
VCC-BH_4: C62.1 U12.3 U14.9 | length 4.7
  Top Layer w0.254: U12.3@69.71,76.005 69.71,76.596 70.173,77.059 71.576,77.059 71.758,77.241 71.758,77.722 71.983,77.946 71.983,78.063 72.016,78.095 U14.9@72.016,78.937
VCC-BH_5: C93.1 U19.3 U21.9 | length 5.1
  Top Layer w0.254: U19.3@69.532,146.427 69.532,147.194 69.868,147.531 71.335,147.531 71.727,147.922 71.727,147.985 71.9,148.158 C93.1@72.1,148.158 ; C93.1@72,148.158 72.111,148.268 72.111,148.69 72.284,148.863 U21.9@72.284,149.35
ZVD1_2: pad.P6@9.216,1 U3.7 | length 13.9
  Top Layer w0.254: v1(19.063,3.936) U3.7@19.063,5.251
  Layer 4 w0.254: v1(9.25,3.454) 9.26,3.464 18.497,3.464 18.97,3.936 v1(19.063,3.936)
  Bottom Layer 1 w0.254: pad.P6@9.216,1 9.431,1.215 9.431,3.179 9.25,3.36 v1(9.25,3.454)
ZVD2_5: pad.P6@9.216,138.962 U17.7 | length 7.4
  Bottom Layer 1 w0.254: pad.P6@9.216,138.962 9.317,139.063 9.317,141.255 9.25,141.322 v1(9.25,141.416) 12.366,141.416 12.95,142 U17.7@12.95,142.922
pads on no net: FID1.1 FID2.1 FID3.1 U6.1 U6.5 U6.12 U6.13 U6.15 U7.1 U7.5 U7.12 U7.13 U7.15 U13.1 U13.5 U13.12 U13.13 U13.15 U14.1 U14.5 U14.12 U14.13 U14.15 U20.1 U20.5 U20.12 U20.13 U20.15 U21.1 U21.5 U21.12 U21.13 U21.15

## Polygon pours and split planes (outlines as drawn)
B-_5 on Top Layer "TOP_LAYER_B-_5_P506" (solid, remove dead copper, pour order 506): 4.98,141.039 4.996,147.538 6.167,147.538 8.392,149.763 8.392,151.273 20.538,151.273 20.538,141.735 19.802,141 16.766,141 16.766,138.955 14.15,138.955 14.15,141.039
Pri-Middle_5 on Top Layer "TOP_LAYER_PRI-MIDDLE_5_P565" (solid, remove dead copper, pour order 565): 33.543,145.589 33.956,145.175 33.956,141.04 32.563,141.04 32.5,140.962 32.5,139.462 29.993,139.462 29.993,145.055 30.526,145.589
54Vout_5 on Top Layer "TOP_LAYER_54VOUT_5_P558" (solid, remove dead copper, pour order 558): 65.149,159.213 70.919,159.213 72.142,157.989 72.142,157.024 72.027,156.908 65.149,156.908
PGND_5 on Top Layer "TOP_LAYER_PGND_5_P557" (solid, remove dead copper, pour order 557): 71,151.396 64.117,151.396 64.015,151.498 64.015,152.81 66.75,155.545 70.263,155.545 71,154.808
PGND_5 on Top Layer "TOP_LAYER_PGND_5_P552" (solid, remove dead copper, pour order 552): 70.376,168.55 63.629,168.55 63.417,168.338 63.417,166.409 63.696,166.129 70.522,166.129 70.71,166.317 70.71,168.217
54Vout_5 on Top Layer "TOP_LAYER_54VOUT_5_P551" (solid, remove dead copper, pour order 551): 63.244,169.78 63.244,172.471 63.233,172.482 70.303,172.482 70.303,169.807 69.96,169.463 63.56,169.463
54Vout_5 on Top Layer "TOP_LAYER_54VOUT_5_P550" (solid, remove dead copper, pour order 550): 64.25,144.057 68.731,144.057 68.731,141.847 68.096,141.847 66.706,140.457 66.706,138.542 66.268,138.104 64.25,138.104
PGND_4 on Top Layer "TOP_LAYER_PGND_4_P549" (solid, remove dead copper, pour order 549): 70.376,98.55 63.629,98.55 63.417,98.338 63.417,96.409 63.696,96.129 70.522,96.129 70.71,96.317 70.71,98.217
54Vout_4 on Top Layer "TOP_LAYER_54VOUT_4_P548" (solid, remove dead copper, pour order 548): 63.244,99.798 63.244,102.489 63.233,102.5 70.303,102.5 70.303,99.825 69.96,99.482 63.56,99.482
PGND_4 on Top Layer "TOP_LAYER_PGND_4_P547" (solid, remove dead copper, pour order 547): 71,80.995 64.517,80.995 64.015,81.498 64.015,82.81 66.75,85.545 70.263,85.545 71,84.808
Sec-SWB_4 on Top Layer "TOP_LAYER_SEC-SWB_4_P546" (solid, remove dead copper, pour order 546): 70.935,78.58 68.71,76.205 68.71,74.236 64.015,74.236 64.015,80.173 64.403,80.561 70.935,80.561 70.943,80.553
54Vout_4 on Top Layer "TOP_LAYER_54VOUT_4_P545" (solid, remove dead copper, pour order 545): 64.25,73.798 69.362,73.798 69.362,71.743 68.477,71.743 66.784,70.049 66.784,68.135 66.649,68 64.25,68
54Vout_2 on Top Layer "TOP_LAYER_54VOUT_2_P376" (solid, remove dead copper, pour order 376): 64.25,5.798 64.404,5.953 69.362,5.953 69.362,3.743 68.477,3.743 66.784,2.049 66.784,0.135 66.649,0 64.25,0
54Vout_4 on Top Layer "TOP_LAYER_54VOUT_4_P542" (solid, remove dead copper, pour order 542): 65.754,89.252 70.647,89.252 70.774,89.126 70.768,87.243 70.036,86.511 66.013,86.511 65.754,86.77
Sec-SWA_5 on Top Layer "TOP_LAYER_SEC-SWA_5_P540" (solid, remove dead copper, pour order 540): 65.924,151.801 66.706,151.019 71.061,151.019 71.051,148.832 68.008,145.789 68.008,144.665 63.531,144.665 63,145.196 63,151.801
Pri-SW_5 on Top Layer "TOP_LAYER_PRI-SW_5_P507" (solid, remove dead copper, pour order 507): 5.348,152.942 5.37,162.347 8.796,165.772 23.215,165.772 23.215,156.103 20.054,152.942
B-_5 on Top Layer "TOP_LAYER_B-_5_P505" (solid, remove dead copper, pour order 505): 5.504,172.439 19.75,172.439 19.75,170.9 5.504,170.9
B+_5 on Top Layer "TOP_LAYER_B+_5_P504" (solid, remove dead copper, pour order 504): 5.478,169.47 19.75,169.47 19.75,167.309 5.478,167.309
Sec-SWB_4 on Top Layer "TOP_LAYER_SEC-SWB_4_P490" (solid, remove dead copper, pour order 490): 34 vertices, not listed, extent 40.128,73.519 70.946,100.408
Sec-SWA_5 on Top Layer "TOP_LAYER_SEC-SWA_5_P473" (solid, remove dead copper, pour order 473): 34 vertices, not listed, extent 40.77,143.519 71.29,170.408
B-_2 on Top Layer "TOP_LAYER_B-_2_P407" (solid, remove dead copper, pour order 407): 5.531,34.439 20.668,34.439 20.866,34.241 20.866,33.254 5.531,33.254
Sec-SWA_2 on Top Layer "TOP_LAYER_SEC-SWA_2_P372" (solid, remove dead copper, pour order 372): 34 vertices, not listed, extent 40.763,5.519 70.946,32.408
54Vout_2 on Top Layer "TOP_LAYER_54VOUT_2_P442" (solid, remove dead copper, pour order 442): 63.244,31.798 63.244,34.489 63.233,34.5 70.303,34.5 70.303,31.825 69.96,31.482 63.56,31.482
PGND_2 on Top Layer "TOP_LAYER_PGND_2_P441" (solid, remove dead copper, pour order 441): 70.376,30.55 63.629,30.55 63.417,30.338 63.417,28.409 63.696,28.129 70.522,28.129 70.71,28.317 70.71,30.217
Sec-SWA_2 on Top Layer "TOP_LAYER_SEC-SWA_2_P440" (solid, remove dead copper, pour order 440): 70.529,27.614 63.819,27.614 63,26.795 63,22.754 63.956,21.799 70.446,21.799 70.694,22.046 70.694,27.449
B+_2 on Top Layer "TOP_LAYER_B+_2_P406" (solid, remove dead copper, pour order 406): 5.514,32.031 20.525,32.031 20.866,31.69 20.866,29.563 20.583,29.28 5.514,29.28
B-_2 on Top Layer "TOP_LAYER_B-_2_P400" (solid, remove dead copper, pour order 400): 14.231,-0.25 14.231,3 10.908,3.018 10.908,13.421 21.607,13.421 21.607,7.107 21.197,6.697 16.327,6.697 15.878,6.248 15.878,3.985 16.788,3.196 16.788,-0.25
Pri-Middle_2 on Top Layer "TOP_LAYER_PRI-MIDDLE_2_P399" (solid, remove dead copper, pour order 399): 30.837,7.42 33.31,7.42 33.368,7.363 33.368,3.773 32.294,2.7 32.294,1 29.993,1 29.993,2.931 30.608,3.547 30.608,7.192
PGND_2 on Top Layer "TOP_LAYER_PGND_2_P378" (solid, remove dead copper, pour order 378): 71,12.995 64.517,12.995 64.015,13.498 64.015,14.81 66.858,17.545 70.263,17.545 71,16.808
Sec-SWA_2 on Top Layer "TOP_LAYER_SEC-SWA_2_P377" (solid, remove dead copper, pour order 377): 70.898,6.424 64.015,6.424 64.015,12.173 64.403,12.561 70.935,12.561 70.943,12.553
Pri-SW_2 on Top Layer "TOP_LAYER_PRI-SW_2_P365" (solid, remove dead copper, pour order 365): 10.995,15.293 21.332,15.293 23.489,17.449 23.489,27.139 23.033,27.595 10.995,27.595
Pri-Mid1_2 on Layer 6 "LAYER_6_PRI-MID1_2_P626" (solid, remove dead copper, pour order 626): 18 vertices, not listed, extent 22.496,3.231 37.639,14.568
Pri-SW_2 on Layer 6 "LAYER_6_PRI-SW_2_P428" (solid, remove dead copper, pour order 428): 5.563,28.123 21.741,28.123 21.741,15.654 21.097,15.01 5.531,15.01
Pri-SW_5 on Layer 6 "LAYER_6_PRI-SW_5_P467" (solid, remove dead copper, pour order 467): 47 vertices, not listed, extent 21.519,143.513 62.909,170.403
PGND_5 on Layer 6 "LAYER_6_PGND_5_P591" (solid, remove dead copper, pour order 591): 63.411,172.5 63.411,157.14 64.517,157.14 64.517,154.298 63.411,154.215 63.411,141.301 67.201,141.301 67.201,138 75,138 75,172.5
Pri-SW_2 on Layer 6 "LAYER_6_PRI-SW_2_P592" (solid, remove dead copper, pour order 592): 22.85,34.483 25.944,34.483 26.013,34.414 25.944,30.629 24.951,29.934 22.85,29.934
PGND_4 on Layer 6 "LAYER_6_PGND_4_P590" (solid, remove dead copper, pour order 590): 63.232,102.204 63.232,96.409 64.583,87.903 65.169,87.318 65.169,83.909 64.342,83.083 63.232,83.084 63.232,71.004 67.129,71.004 67.129,67.704 74.928,67.704 74.928,102.204
PGND_2 on Layer 6 "LAYER_6_PGND_2_P434" (solid, remove dead copper, pour order 434): 63.304,34.5 63.304,19.14 64.517,19.14 64.517,16.298 63.304,16.207 63.304,3.301 67.201,3.301 67.201,0 75,0 75,34.5
Pri-Middle_5 on Layer 6 "LAYER_6_PRI-MIDDLE_5_P560" (solid, remove dead copper, pour order 560): 33.543,145.589 33.956,145.175 33.956,141.04 32.563,141.04 32.5,140.962 32.5,139.462 29.993,139.462 29.993,145.055 30.526,145.589
Pri-SW_2 on Layer 6 "LAYER_6_PRI-SW_2_P390" (solid, remove dead copper, pour order 390): 41 vertices, not listed, extent 36.705,37.799 64.006,64.687
B-_5 on Layer 6 "LAYER_6_B-_5_P533" (solid, remove dead copper, pour order 533): 4.985,141.046 5.001,147.544 6.172,147.544 8.397,149.769 8.397,151.279 20.543,151.279 20.543,141.742 19.807,141.006 16.771,141.006 16.771,138.962 14.155,138.962 14.155,141.046
Pri-SW_5 on Layer 6 "LAYER_6_PRI-SW_5_P537" (solid, remove dead copper, pour order 537): 5.348,152.942 5.372,163.134 8.011,165.772 21.125,165.772 21.125,154.013 20.054,152.942
Pri-Mid1_5 on Layer 6 "LAYER_6_PRI-MID1_5_P522" (solid, remove dead copper, pour order 522): 18 vertices, not listed, extent 22.33,141.522 37.473,152.859
B+_5 on Layer 6 "LAYER_6_B+_5_P518" (solid, remove dead copper, pour order 518): 5.498,169.581 21.308,169.581 21.308,167.42 5.498,167.42
B-_5 on Layer 6 "LAYER_6_B-_5_P517" (solid, remove dead copper, pour order 517): 5.498,172.468 21.325,172.468 21.325,170.307 5.498,170.307
Sec-SWB_4 on Layer 6 "LAYER_6_SEC-SWB_4_P498" (solid, remove dead copper, pour order 498): 40 vertices, not listed, extent 39.337,73.519 64.823,100.408
Pri-SW_5 on Layer 6 "LAYER_6_PRI-SW_5_P485" (solid, remove dead copper, pour order 485): 36 vertices, not listed, extent 37.67,107.799 63.766,134.687
B-_2 on Layer 6 "LAYER_6_B-_2_P465" (solid, remove dead copper, pour order 465): 5.515,34.219 5.735,34.439 22.243,34.439 22.243,33.254 5.515,33.254
Pri-SW_2 on Layer 6 "LAYER_6_PRI-SW_2_P453" (solid, remove dead copper, pour order 453): 44 vertices, not listed, extent 22.666,5.484 62.771,32.374
B-_2 on Layer 6 "LAYER_6_B-_2_P430" (solid, remove dead copper, pour order 430): 10.906,14.007 21.581,14.007 21.581,5.255 19.327,3 16.75,3 16.75,0.955 14.231,0.955 14.231,3.039 10.88,3.039
12Vp_2 on Layer 6 "LAYER_6_12VP_2_P419" (solid, remove dead copper, pour order 419): 5.5,9.945 8.693,13.138 10.372,13.138 10.473,13.037 10.473,3.377 9.839,2.743 9.839,0.768 5.532,0.768 5.5,0.8
Pri-Middle_2 on Layer 6 "LAYER_6_PRI-MIDDLE_2_P375" (solid, remove dead copper, pour order 375): 33.543,7.627 33.956,7.214 33.956,3.473 31.984,1.5 29.993,1.5 29.993,7.094 30.526,7.627
Pri-Mid1_2 on Layer 3 "LAYER_3_PRI-MID1_2_P630" (solid, remove dead copper, pour order 630): 28.985,3.454 27.118,3.454 27.118,9.203 37.639,9.203 37.639,8.185 37.639,3.231 34.783,3.231 34.783,7.598 34.286,8.095 29.878,8.095 29.273,7.489 29.273,3.742
Pri-Mid1_5 on Layer 3 "LAYER_3_PRI-MID1_5_P624" (solid, remove dead copper, pour order 624): 28.819,141.744 26.926,141.744 26.926,147.57 37.473,147.57 37.473,146.475 37.473,141.522 34.617,141.522 34.617,145.888 34.12,146.385 29.713,146.385 29.107,145.78 29.107,142.032
Pri-Middle_5 on Layer 3 "LAYER_3_PRI-MIDDLE_5_P619" (solid, remove dead copper, pour order 619): 33.543,145.589 33.956,145.175 33.956,141.04 32.563,141.04 32.5,140.962 32.5,139.462 29.993,139.462 29.993,145.055 30.526,145.589
Pri-SW_5 on Layer 3 "LAYER_3_PRI-SW_5_P615" (solid, remove dead copper, pour order 615): 35 vertices, not listed, extent 39.068,107.799 63.766,134.687
54Vout_5 on Layer 3 "LAYER_3_54VOUT_5_P600" (solid, remove dead copper, pour order 600): 69.851,145.929 69.851,138 64.25,138 64.25,141.018 63.282,141.018 63.282,144.074 68.576,144.074
Sec-SWA_5 on Layer 3 "LAYER_3_SEC-SWA_5_P583" (solid, remove dead copper, pour order 583): 41 vertices, not listed, extent 39.371,143.539 71.046,170.428
5V-s_5 on Layer 3 "LAYER_3_5V-S_5_P602" (solid, remove dead copper, pour order 602): 75,172.489 75,138 70.214,138 70.214,146.415 71.272,148.146 71.272,172.489
54Vout_5 on Layer 3 "LAYER_3_54VOUT_5_P601" (solid, remove dead copper, pour order 601): 70.946,156.744 70.946,172.5 63.282,172.5 63.282,156.744
5V-s_4 on Layer 3 "LAYER_3_5V-S_4_P599" (solid, remove dead copper, pour order 599): 75,102.489 75,68 70.214,68 70.214,76.415 71.272,77.853 71.272,102.489
54Vout_4 on Layer 3 "LAYER_3_54VOUT_4_P598" (solid, remove dead copper, pour order 598): 70.946,86.744 70.946,102.5 63.282,102.5 63.282,86.744
54Vout_4 on Layer 3 "LAYER_3_54VOUT_4_P597" (solid, remove dead copper, pour order 597): 69.851,75.696 69.851,68 64.25,68 64.25,71.018 63.282,71.018 63.282,73.711 68.487,73.711
5V-s_2 on Layer 3 "LAYER_3_5V-S_2_P596" (solid, remove dead copper, pour order 596): 75,34.489 75,0 70.214,0 70.214,8.415 71.272,9.473 71.272,34.489
54Vout_2 on Layer 3 "LAYER_3_54VOUT_2_P572" (solid, remove dead copper, pour order 572): 69.851,7.929 69.851,0 64.25,0 64.25,3.018 63.282,3.018 63.282,5.929 68.476,5.929
54Vout_2 on Layer 3 "LAYER_3_54VOUT_2_P571" (solid, remove dead copper, pour order 571): 70.946,18.744 70.946,34.5 63.282,34.5 63.282,18.744
12Vp_2 on Layer 3 "LAYER_3_12VP_2_P585" (solid, remove dead copper, pour order 585): 5.5,9.945 8.832,13.277 10.233,13.277 10.473,13.037 10.473,3.377 9.839,2.743 9.839,0.768 5.532,0.768 5.5,0.8
PGND_5 on Layer 3 "LAYER_3_PGND_5_P584" (solid, remove dead copper, pour order 584): 65.262,156.262 70.126,156.262 71,155.389 71,151.595 70.492,151.087 67.606,151.087 65.262,153.431
PGND_4 on Layer 3 "LAYER_3_PGND_4_P582" (solid, remove dead copper, pour order 582): 65.262,86.262 70.37,86.262 71,85.633 71,81.595 70.492,81.087 67.606,81.087 65.262,83.431
Sec-SWB_4 on Layer 3 "LAYER_3_SEC-SWB_4_P581" (solid, remove dead copper, pour order 581): 41 vertices, not listed, extent 38.647,73.539 71.046,100.428
Pri-SW_2 on Layer 3 "LAYER_3_PRI-SW_2_P370" (solid, remove dead copper, pour order 370): 50 vertices, not listed, extent 22.665,37.431 64.006,64.624
B-_5 on Layer 3 "LAYER_3_B-_5_P536" (solid, remove dead copper, pour order 536): 4.985,141.046 5.001,147.544 5.762,147.544 8.397,150.179 8.397,150.412 20.543,150.412 20.543,141.742 19.807,141.006 16.771,141.006 16.771,138.962 14.155,138.962 14.155,141.046
B-_5 on Layer 3 "LAYER_3_B-_5_P528" (solid, remove dead copper, pour order 528): 5.504,172.439 20.641,172.439 20.839,172.241 20.839,170.307 5.504,170.307
B+_5 on Layer 3 "Layer 3-B+_5" (solid, remove dead copper, pour order 523): 5.5,151.038 21.238,151.038 21.238,140.962 22.243,140.962 22.243,139.303 24.784,139.303 24.784,140.962 26.28,140.962 26.28,155.912 20.899,158.573 20.899,169.482 5.5,169.482
Pri-SW_5 on Layer 3 "LAYER_3_PRI-SW_5_P470" (solid, remove dead copper, pour order 470): 17 vertices, not listed, extent 21.519,157.328 27.459,172.5
PGND_2 on Layer 3 "LAYER_3_PGND_2_P439" (solid, remove dead copper, pour order 439): 65.262,18.262 70.37,18.262 71,17.633 71,13.595 70.492,13.087 67.606,13.087 65.262,15.431
Sec-SWA_2 on Layer 3 "LAYER_3_SEC-SWA_2_P374" (solid, remove dead copper, pour order 374): 41 vertices, not listed, extent 39.371,5.539 71.046,32.428
B-_2 on Layer 3 "LAYER_3_B-_2_P421" (solid, remove dead copper, pour order 421): 10.904,12.861 20.565,12.861 20.565,4.238 19.327,3 16.75,3 16.75,0.955 14.231,0.955 14.231,3.039 10.88,3.039
B+_2 on Layer 3 "LAYER_3_B+_2_P368" (solid, remove dead copper, pour order 368): 5.563,18.675 11.039,13.198 20.543,13.198 20.97,12.771 20.97,3 22.243,3 22.243,1.492 26.28,1.492 26.289,22.483 25.051,23.284 25.051,26.902 21.821,30.133 21.821,32.579 5.563,32.579
B-_2 on Layer 3 "LAYER_3_B-_2_P411" (solid, remove dead copper, pour order 411): 5.531,34.439 21.945,34.439 21.945,33.254 5.531,33.254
